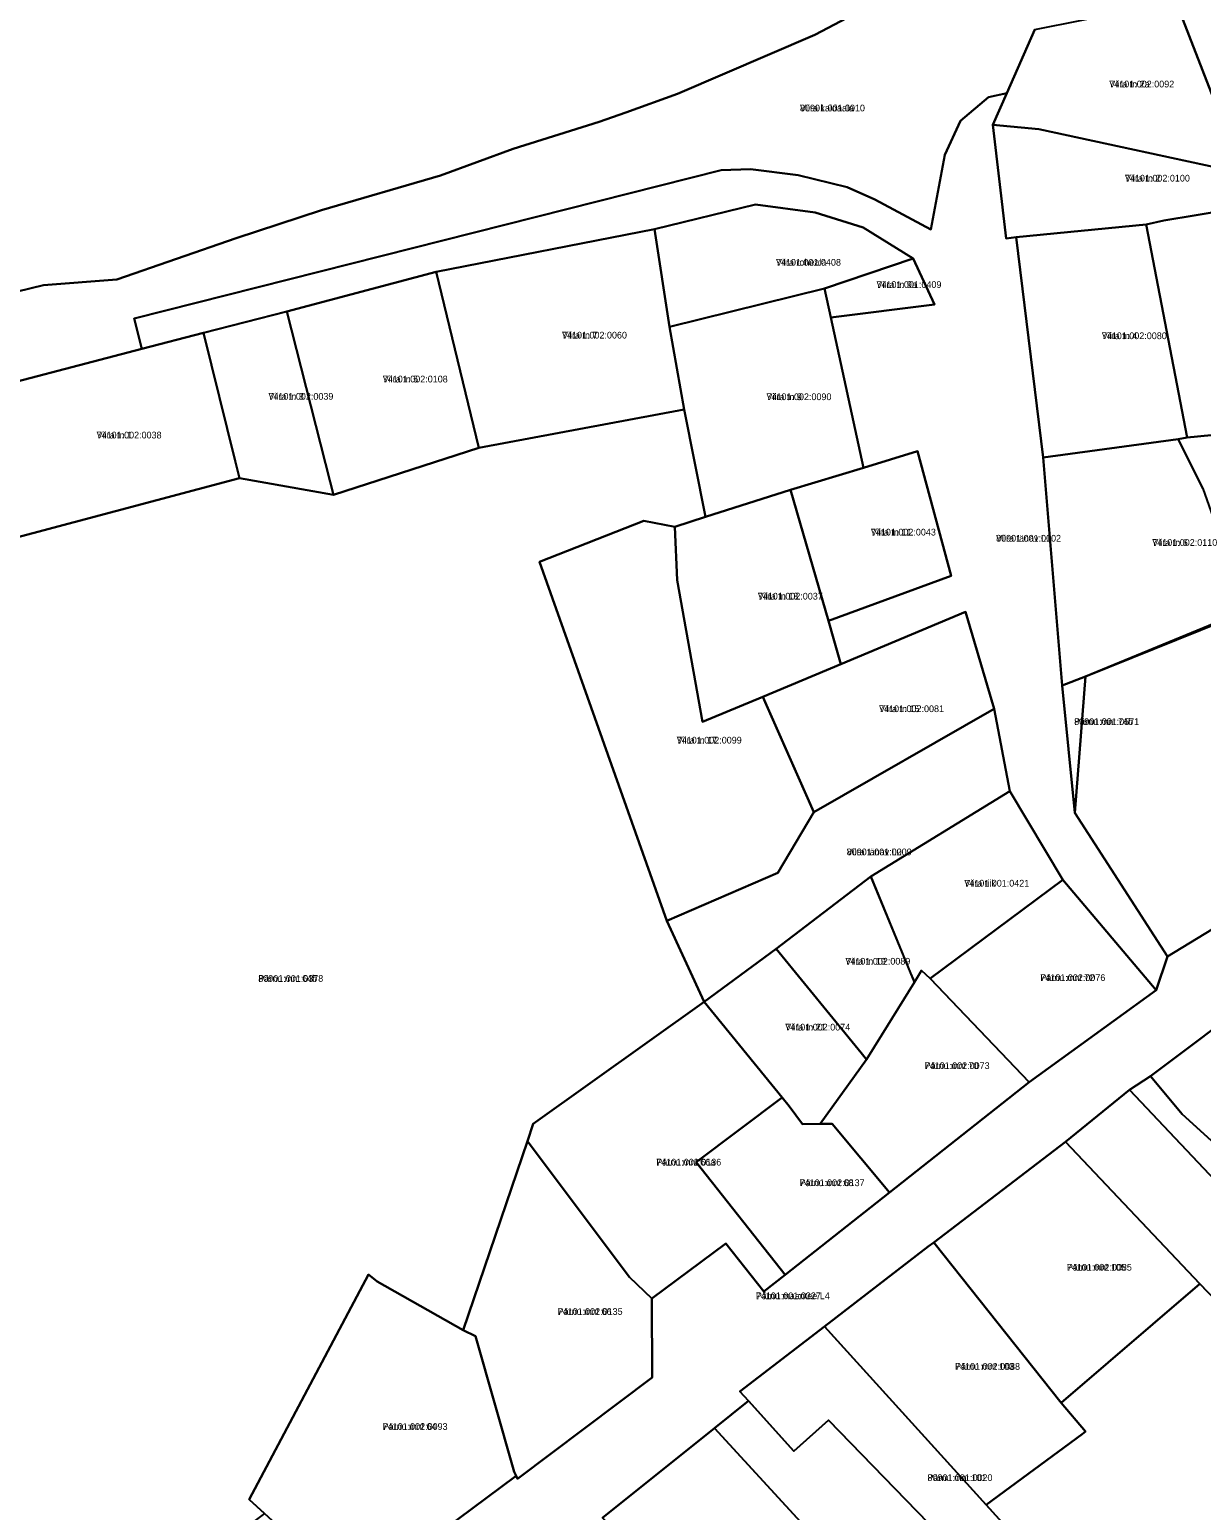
# Model space of a CAD drawing. Extents: x 524000 to 564260, y 6469338 to 6496391.
# Drawn here: x 539303.8 to 539565.4, y 6475121.9 to 6475452.4 of the extents above; entities that cross this region are included whole.
import ezdxf

# ---------------------------------------------------------------- set-up
doc = ezdxf.new("R2010")
doc.units = 0
for name, color, linetype in [('L_AADRESS', 7, 'Continuous'), ('PIIR', 7, 'Continuous'), ('TUNNUS', 7, 'Continuous')]:
    doc.layers.add(name, color=color, linetype=linetype)

msp = doc.modelspace()

# ---------------------------------------------------------------- linework, layer by layer
at = {"layer": 'PIIR'}
for points in [[(539289.12, 6475390.98), (539306.91, 6475395.33), (539323.31, 6475396.58), (539349.93, 6475405.84), (539368.97, 6475412.07), (539395.53, 6475419.79), (539411.79, 6475425.76), (539431, 6475431.76), (539436.9, 6475433.87), (539448.43, 6475437.99), (539479.15, 6475451.2), (539493.56, 6475458.78)], [(539493.56, 6475458.78), (539479.15, 6475451.2), (539448.43, 6475437.99), (539436.9, 6475433.87), (539431, 6475431.76), (539411.79, 6475425.76), (539395.53, 6475419.79), (539368.97, 6475412.07), (539349.93, 6475405.84), (539323.31, 6475396.58), (539306.91, 6475395.33), (539289.12, 6475390.98)], [(539584.75, 6475454.08), (539587.21, 6475451.69), (539593.35, 6475448.75), (539605.5, 6475443.71), (539620, 6475439.58), (539626.79, 6475437.63), (539631.18, 6475435.72), (539634.08, 6475435.02), (539634.87, 6475434.87), (539637.56, 6475427.34), (539618.91, 6475431.9), (539602.06, 6475436.31), (539605.25, 6475427.37), (539577.22, 6475417.54), (539574.57, 6475420.29), (539559.71, 6475458.6)], [(539528.25, 6475452.4), (539522, 6475438.19), (539517.89, 6475437.31), (539511.62, 6475432.01), (539508.11, 6475424.42), (539505.04, 6475407.74), (539492.52, 6475414.42), (539486.35, 6475417.18), (539475.37, 6475419.9), (539464.73, 6475421.25), (539458.25, 6475420.98), (539327.15, 6475387.89), (539328.92, 6475381.12), (539286.73, 6475370.14)], [(539295.23, 6475337.55), (539350.69, 6475352.27), (539371.64, 6475348.56), (539404.12, 6475358.99), (539449.99, 6475367.58), (539454.72, 6475343.6), (539447.84, 6475341.41), (539440.94, 6475342.71), (539417.67, 6475333.57), (539446.06, 6475253.45), (539454.39, 6475235.4), (539416.27, 6475208.15), (539414.96, 6475204.32), (539400.63, 6475162.15), (539381.45, 6475172.98), (539379.48, 6475174.52), (539352.83, 6475124.35), (539356.29, 6475121.18), (539340.27, 6475109.17), (539353.64, 6475090.16), (539301.46, 6475069.45)], [(539565.76, 6475349.97), (539560.27, 6475360.93), (539562.28, 6475361.31), (539570.64, 6475362.17)], [(539825.05, 6475318.59), (539783.21, 6475307.29), (539753.26, 6475298.36), (539727.91, 6475291.35), (539702.52, 6475284.02), (539693.91, 6475281.72), (539676.62, 6475276.83), (539673.86, 6475276.05), (539652.11, 6475269.61), (539625.32, 6475261.18), (539600.82, 6475251.16), (539578.24, 6475236.96), (539554.03, 6475218.82), (539549.38, 6475215.78), (539535.08, 6475204.14), (539505.71, 6475181.68), (539504.39, 6475180.77), (539481.3, 6475162.97), (539462.39, 6475148.47), (539464.3, 6475146.34), (539456.7, 6475140.24), (539431.73, 6475120.22)], [(539376.38, 6475102.78), (539412.45, 6475129.6), (539412.74, 6475128.98), (539442.79, 6475151.58), (539442.75, 6475169.22), (539459.24, 6475181.47), (539467.76, 6475170.76), (539472.51, 6475174.5), (539495.8, 6475192.85), (539526.96, 6475217.45), (539555.3, 6475238), (539557.87, 6475245.52), (539602.92, 6475272.93)]]:
    msp.add_lwpolyline(points, dxfattribs=at)
for points in [[(539529.14, 6475430.13), (539518.89, 6475431.12), (539522, 6475438.19), (539528.25, 6475452.4), (539559.71, 6475458.6), (539574.57, 6475420.29)], [(539328.92, 6475381.12), (539327.15, 6475387.89), (539458.25, 6475420.98), (539464.73, 6475421.25), (539475.37, 6475419.9), (539486.35, 6475417.18), (539492.52, 6475414.42), (539505.04, 6475407.74), (539508.11, 6475424.42), (539511.62, 6475432.01), (539517.89, 6475437.31), (539522, 6475438.19), (539518.89, 6475431.12), (539521.82, 6475405.77), (539524.1, 6475406.02), (539530.08, 6475356.89), (539534.36, 6475306.01), (539537.14, 6475277.55), (539557.87, 6475245.52), (539555.3, 6475238), (539534.49, 6475262.64), (539522.64, 6475282.43), (539519.18, 6475300.8), (539512.77, 6475322.4), (539484.96, 6475310.78), (539483.32, 6475316.51), (539482.19, 6475320.39), (539509.59, 6475330.46), (539502.06, 6475358.26), (539489.97, 6475354.54), (539482.69, 6475388.1), (539505.81, 6475390.99), (539501.08, 6475401.31), (539489.9, 6475408.18), (539479.22, 6475411.55), (539465.91, 6475413.31), (539443.34, 6475407.86), (539394.59, 6475398.32), (539361.23, 6475389.43), (539342.64, 6475384.69)], [(539518.89, 6475431.12), (539529.14, 6475430.13), (539574.57, 6475420.29), (539577.22, 6475417.54), (539578.69, 6475413.3), (539557.02, 6475409.74), (539553.12, 6475408.9), (539524.1, 6475406.02), (539521.82, 6475405.77)], [(539446.69, 6475386.06), (539443.34, 6475407.86), (539465.91, 6475413.31), (539479.22, 6475411.55), (539489.9, 6475408.18), (539501.08, 6475401.31), (539481.31, 6475394.59)], [(539578.69, 6475413.3), (539593.81, 6475370.3), (539570.64, 6475362.17), (539562.28, 6475361.31), (539553.12, 6475408.9), (539557.02, 6475409.74)], [(539553.12, 6475408.9), (539562.28, 6475361.31), (539560.27, 6475360.93), (539530.08, 6475356.89), (539524.1, 6475406.02)], [(539443.34, 6475407.86), (539446.69, 6475386.06), (539449.99, 6475367.58), (539404.12, 6475358.99), (539394.59, 6475398.32)], [(539370.9, 6475351.47), (539361.23, 6475389.43), (539394.59, 6475398.32), (539404.12, 6475358.99), (539371.64, 6475348.56)], [(539481.31, 6475394.59), (539501.08, 6475401.31), (539505.81, 6475390.99), (539482.69, 6475388.1)], [(539449.99, 6475367.58), (539446.69, 6475386.06), (539481.31, 6475394.59), (539482.69, 6475388.1), (539489.97, 6475354.54), (539473.68, 6475349.65), (539454.72, 6475343.6)], [(539342.64, 6475384.69), (539361.23, 6475389.43), (539370.9, 6475351.47), (539371.64, 6475348.56), (539350.69, 6475352.27), (539349.73, 6475356.15)], [(539286.73, 6475370.14), (539328.92, 6475381.12), (539342.64, 6475384.69), (539349.73, 6475356.15), (539350.69, 6475352.27), (539295.23, 6475337.55), (539294.47, 6475340.45)], [(539560.27, 6475360.93), (539565.76, 6475349.97), (539578.83, 6475312.86), (539572.41, 6475308.38), (539568.26, 6475319.86), (539539.55, 6475307.99), (539534.36, 6475306.01), (539530.08, 6475356.89)], [(539473.68, 6475349.65), (539489.97, 6475354.54), (539502.06, 6475358.26), (539509.59, 6475330.46), (539482.19, 6475320.39)], [(539483.32, 6475316.51), (539484.96, 6475310.78), (539467.52, 6475303.49), (539454.05, 6475297.86), (539448.4, 6475329.53), (539447.84, 6475341.41), (539454.72, 6475343.6), (539473.68, 6475349.65), (539482.19, 6475320.39)], [(539417.67, 6475333.57), (539440.94, 6475342.71), (539447.84, 6475341.41), (539448.4, 6475329.53), (539454.05, 6475297.86), (539467.52, 6475303.49), (539478.93, 6475277.7), (539470.83, 6475264.18), (539446.06, 6475253.45)], [(539467.52, 6475303.49), (539484.96, 6475310.78), (539512.77, 6475322.4), (539519.18, 6475300.8), (539478.93, 6475277.7), (539469.48, 6475299.06)], [(539578.83, 6475312.86), (539602.92, 6475272.93), (539557.87, 6475245.52), (539537.14, 6475277.55), (539539.55, 6475307.99), (539570.19, 6475320.31), (539572.41, 6475308.38)], [(539539.55, 6475307.99), (539537.14, 6475277.55), (539534.36, 6475306.01)], [(539454.39, 6475235.4), (539446.06, 6475253.45), (539470.83, 6475264.18), (539478.93, 6475277.7), (539519.18, 6475300.8), (539522.64, 6475282.43), (539491.59, 6475263.37), (539470.52, 6475247.25)], [(539501.36, 6475239.81), (539491.59, 6475263.37), (539522.64, 6475282.43), (539534.49, 6475262.64), (539504.85, 6475240.58), (539502.97, 6475242.41)], [(539491.59, 6475263.37), (539500.51, 6475241.83), (539501.36, 6475239.81), (539494.08, 6475228.06), (539490.64, 6475222.55), (539489.49, 6475223.99), (539470.52, 6475247.25)], [(539504.85, 6475240.58), (539534.49, 6475262.64), (539555.3, 6475238), (539526.96, 6475217.45)], [(539470.52, 6475247.25), (539489.49, 6475223.99), (539490.64, 6475222.55), (539480.31, 6475208.14), (539476.35, 6475208.07), (539473.36, 6475212.15), (539471.82, 6475214.04), (539454.39, 6475235.4)], [(539483.01, 6475208.19), (539480.31, 6475208.14), (539490.64, 6475222.55), (539494.08, 6475228.06), (539501.36, 6475239.81), (539502.97, 6475242.41), (539504.85, 6475240.58), (539526.96, 6475217.45), (539495.8, 6475192.85)], [(539554.03, 6475218.82), (539578.24, 6475236.96), (539615.58, 6475191.51), (539597.66, 6475177.19), (539561.15, 6475210.35)], [(539454.39, 6475235.4), (539471.82, 6475214.04), (539452.6, 6475199.62), (539472.51, 6475174.5), (539467.76, 6475170.76), (539459.24, 6475181.47), (539442.75, 6475169.22), (539437.74, 6475173.97), (539430.78, 6475183.24), (539414.96, 6475204.32), (539416.27, 6475208.15)], [(539605.37, 6475156.48), (539549.38, 6475215.78), (539554.03, 6475218.82), (539561.15, 6475210.35), (539597.66, 6475177.19), (539603.22, 6475172.2), (539612.5, 6475163.41), (539621.61, 6475144.62), (539625.52, 6475135.5), (539642.98, 6475104.01), (539647.08, 6475099.52), (539649.32, 6475097.06), (539649.25, 6475096.88), (539643.46, 6475081.48), (539641.9, 6475084.73), (539626.35, 6475117.08), (539619.33, 6475130.28)], [(539471.82, 6475214.04), (539473.36, 6475212.15), (539476.35, 6475208.07), (539480.31, 6475208.14), (539483.01, 6475208.19), (539495.8, 6475192.85), (539472.51, 6475174.5), (539452.6, 6475199.62)], [(539535.08, 6475204.14), (539549.38, 6475215.78), (539605.37, 6475156.48), (539591.7, 6475144.75), (539565.08, 6475172.46)], [(539414.96, 6475204.32), (539430.78, 6475183.24), (539437.74, 6475173.97), (539442.75, 6475169.22), (539442.79, 6475151.58), (539412.74, 6475128.98), (539412.45, 6475129.6), (539411.99, 6475130.54), (539403.34, 6475160.78), (539400.63, 6475162.15)], [(539534.11, 6475145.91), (539505.71, 6475181.68), (539535.08, 6475204.14), (539565.08, 6475172.46)], [(539517.4, 6475123.15), (539481.3, 6475162.97), (539504.39, 6475180.77), (539505.71, 6475181.68), (539534.11, 6475145.91), (539539.57, 6475139.5), (539538.81, 6475138.94)], [(539411.99, 6475130.54), (539412.45, 6475129.6), (539376.38, 6475102.78), (539356.29, 6475121.18), (539352.83, 6475124.35), (539379.48, 6475174.52), (539381.45, 6475172.98), (539400.63, 6475162.15), (539403.34, 6475160.78)], [(539546.15, 6475091.47), (539544.25, 6475093.57), (539517.4, 6475123.15), (539538.81, 6475138.94), (539539.57, 6475139.5), (539534.11, 6475145.91), (539565.08, 6475172.46), (539591.7, 6475144.75), (539605.37, 6475156.48), (539619.33, 6475130.28), (539571.71, 6475104.85), (539566.99, 6475102.33), (539566.92, 6475102.34), (539561.62, 6475099.53)], [(539474.41, 6475135.12), (539464.3, 6475146.34), (539462.39, 6475148.47), (539481.3, 6475162.97), (539517.4, 6475123.15), (539544.25, 6475093.57), (539546.15, 6475091.47), (539536.43, 6475086.16), (539534.11, 6475088.54), (539482.15, 6475142.07)], [(539514.52, 6475077.34), (539456.7, 6475140.24), (539464.3, 6475146.34), (539474.41, 6475135.12), (539482.15, 6475142.07), (539534.11, 6475088.54), (539536.43, 6475086.16), (539524.57, 6475080.22), (539516.23, 6475075.48)], [(539456.7, 6475140.24), (539514.52, 6475077.34), (539516.23, 6475075.48), (539501.22, 6475066.95), (539489.3, 6475060.62), (539487.12, 6475062.89), (539431.73, 6475120.22)]]:
    msp.add_lwpolyline(points, close=True, dxfattribs=at)

# ---------------------------------------------------------------- texts
at = {"layer": 'L_AADRESS'}
for s, p in [('Viira tn 2a', (539544.85, 6475439.45)), ('Viira kaldaala', (539475.81, 6475434.1)), ('Viira tn 2', (539548.35, 6475418.45)), ('Viira roheala', (539470.45, 6475399.68)), ('Viira tn 9a', (539492.88, 6475394.71)), ('Viira tn 7', (539422.68, 6475383.42)), ('Viira tn 4', (539543.19, 6475383.28)), ('Viira tn 5', (539382.67, 6475373.62)), ('Viira tn 3', (539357.14, 6475369.76)), ('Viira tn 9', (539468.33, 6475369.67)), ('Viira tn 1', (539318.79, 6475361.12)), ('Viira tn 11', (539491.64, 6475339.46)), ('Viira tänav L1', (539519.59, 6475338.1)), ('Viira tn 6', (539554.45, 6475337.15)), ('Viira tn 13', (539466.4, 6475325.17)), ('Viira tn 15', (539493.46, 6475300.05)), ('Pärnu mnt 74b', (539537.02, 6475297.18)), ('Viira tn 17', (539448.3, 6475293.04)), ('Viira tänav L2', (539486.24, 6475268.1)), ('Viira tiik', (539512.49, 6475261.12)), ('Viira tn 19', (539485.94, 6475243.7)), ('Pärnu mnt 64b', (539354.88, 6475239.86)), ('Pärnu mnt 72', (539529.47, 6475240.04)), ('Viira tn 21', (539472.52, 6475229)), ('Pärnu mnt 70', (539503.64, 6475220.4)), ('Pärnu mnt 66a', (539443.73, 6475198.87)), ('Pärnu mnt 68', (539475.73, 6475194.27)), ('Pärnu mnt 105', (539535.39, 6475175.41)), ('Pärnu maantee L4', (539465.96, 6475169.04)), ('Pärnu mnt 66', (539421.71, 6475165.53)), ('Pärnu mnt 103', (539510.43, 6475153.28)), ('Pärnu mnt 64', (539382.64, 6475139.87)), ('Pärnu mnt 101', (539504.27, 6475128.46))]:
    msp.add_text(s, height=1.5, dxfattribs=at).set_placement(p)
at = {"layer": 'TUNNUS'}
for s, p in [('74101:002:0092', (539544.85, 6475439.45)), ('80901:001:0010', (539475.81, 6475434.1)), ('74101:002:0100', (539548.35, 6475418.45)), ('74101:001:0408', (539470.45, 6475399.68)), ('74101:001:0409', (539492.88, 6475394.71)), ('74101:002:0060', (539422.68, 6475383.42)), ('74101:002:0080', (539543.19, 6475383.28)), ('74101:002:0108', (539382.67, 6475373.62)), ('74101:002:0039', (539357.14, 6475369.76)), ('74101:002:0090', (539468.33, 6475369.67)), ('74101:002:0038', (539318.79, 6475361.12)), ('74101:002:0043', (539491.64, 6475339.46)), ('80901:001:0002', (539519.59, 6475338.1)), ('74101:002:0110', (539554.45, 6475337.15)), ('74101:002:0037', (539466.4, 6475325.17)), ('74101:002:0081', (539493.46, 6475300.05)), ('80901:001:0571', (539537.02, 6475297.18)), ('74101:002:0099', (539448.3, 6475293.04)), ('80901:001:0009', (539486.24, 6475268.1)), ('74101:001:0421', (539512.49, 6475261.12)), ('74101:002:0089', (539485.94, 6475243.7)), ('80901:001:0378', (539354.88, 6475239.86)), ('74101:002:0076', (539529.47, 6475240.04)), ('74101:002:0074', (539472.52, 6475229)), ('74101:002:0073', (539503.64, 6475220.4)), ('74101:002:0136', (539443.73, 6475198.87)), ('74101:002:0137', (539475.73, 6475194.27)), ('74101:002:0085', (539535.39, 6475175.41)), ('74101:001:0327', (539465.96, 6475169.04)), ('74101:002:0135', (539421.71, 6475165.53)), ('74101:002:0088', (539510.43, 6475153.28)), ('74101:002:0093', (539382.64, 6475139.87)), ('80901:001:0020', (539504.27, 6475128.46))]:
    msp.add_text(s, height=1.5, dxfattribs=at).set_placement(p)

doc.saveas('drawing.dxf')
